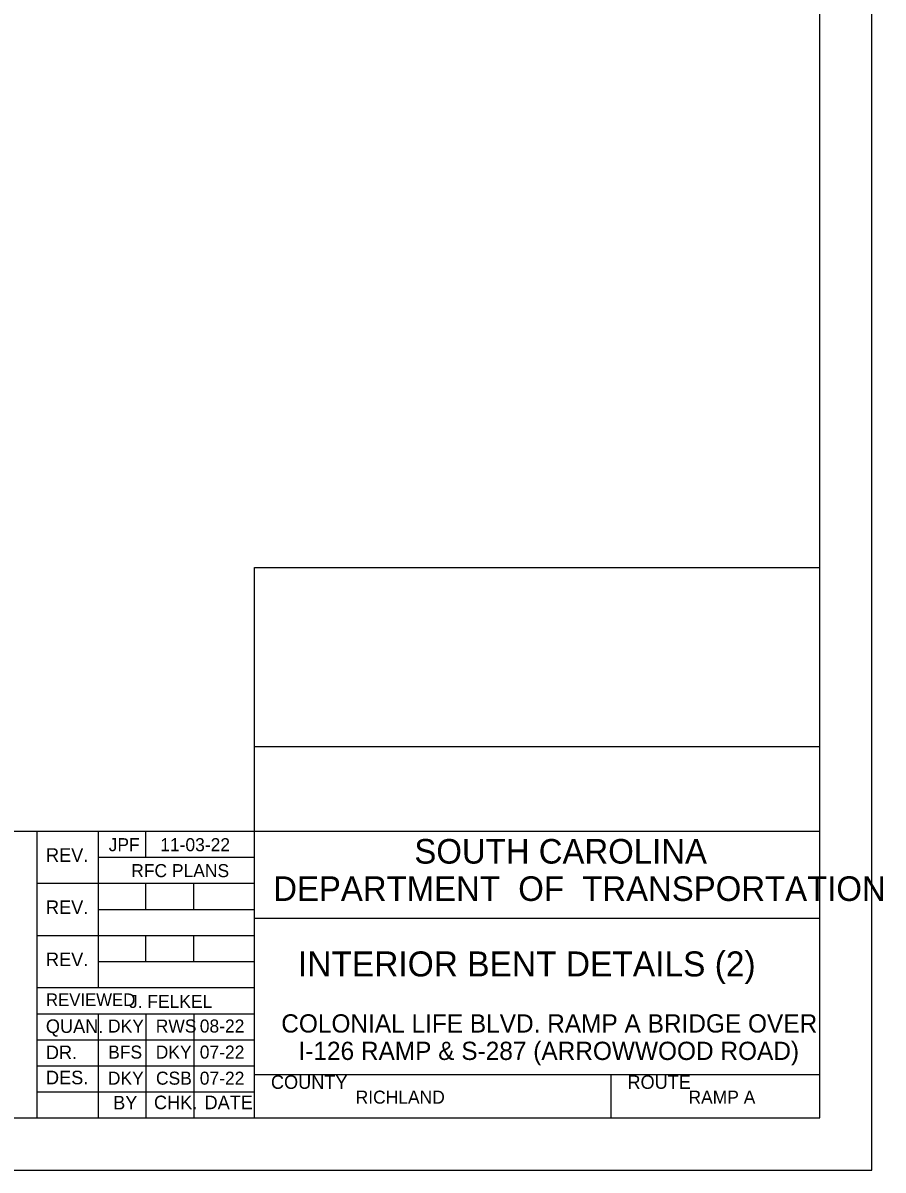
# Model space of a CAD drawing. Extents: x 1970675.2 to 1970711.3, y 796145.2 to 796167.2.
# Drawn here: x 1970703.1 to 1970711.34, y 796145.25 to 796156.25 of the extents above; entities that cross this region are included whole.
import ezdxf

# ---------------------------------------------------------------- set-up
doc = ezdxf.new("R2010")
doc.units = 0
for name, color, linetype in [('BR_BORDER LINES', 7, 'Continuous'), ('BR_TEXT', 7, 'Continuous'), ('Level 31', 7, 'Continuous')]:
    doc.layers.add(name, color=color, linetype=linetype)

msp = doc.modelspace()

# ---------------------------------------------------------------- linework, layer by layer
at = {"layer": 'BR_BORDER LINES'}
for p, q in [((1970710.736, 796145.746), (1970710.736, 796166.746)), ((1970705.319, 796145.746), (1970705.319, 796151.023)), ((1970705.319, 796151.023), (1970710.736, 796151.023)), ((1970705.319, 796149.308), (1970710.736, 796149.308)), ((1970697.87, 796148.496), (1970703.236, 796148.496)), ((1970703.236, 796145.746), (1970703.236, 796148.496)), ((1970703.236, 796148.496), (1970710.736, 796148.496)), ((1970703.819, 796148.496), (1970703.819, 796146.996)), ((1970704.277, 796148.246), (1970704.277, 796148.496)), ((1970703.819, 796148.246), (1970705.319, 796148.246)), ((1970703.236, 796147.996), (1970705.319, 796147.996)), ((1970704.277, 796147.746), (1970704.277, 796147.996)), ((1970704.736, 796147.746), (1970704.736, 796147.996)), ((1970703.819, 796147.746), (1970705.319, 796147.746)), ((1970705.319, 796147.663), (1970705.319, 796147.663)), ((1970705.319, 796147.663), (1970710.736, 796147.663)), ((1970703.236, 796147.496), (1970705.319, 796147.496)), ((1970704.277, 796147.246), (1970704.277, 796147.496)), ((1970704.736, 796147.246), (1970704.736, 796147.496)), ((1970703.819, 796147.246), (1970705.319, 796147.246)), ((1970703.236, 796146.996), (1970705.319, 796146.996)), ((1970703.236, 796146.746), (1970705.319, 796146.746)), ((1970703.819, 796146.746), (1970703.819, 796145.746)), ((1970704.277, 796146.746), (1970704.277, 796145.746)), ((1970704.736, 796146.746), (1970704.736, 796145.746)), ((1970703.236, 796146.496), (1970705.319, 796146.496)), ((1970703.236, 796146.246), (1970705.319, 796146.246)), ((1970705.319, 796146.163), (1970710.736, 796146.163)), ((1970705.417, 796146.163), (1970710.736, 796146.163)), ((1970708.736, 796145.746), (1970708.736, 796146.163)), ((1970703.236, 796145.996), (1970705.319, 796145.996)), ((1970677.07, 796145.746), (1970710.736, 796145.746))]:
    msp.add_line(p, q, dxfattribs=at)
at = {"layer": 'Level 31'}
msp.add_line((1970708.028, 796147.223), (1970708.028, 796147.223), dxfattribs=at)
msp.add_lwpolyline([(1970675.236, 796167.246), (1970675.236, 796145.246), (1970711.236, 796145.246), (1970711.236, 796167.246)], dxfattribs=at)

# ---------------------------------------------------------------- texts
at = {"layer": 'BR_TEXT'}
for s, height, p in [('REV.', 0.13, (1970703.32, 796148.202)), ('JPF', 0.125, (1970703.921, 796148.304)), ('11-03-22', 0.125, (1970704.415, 796148.304)), ('SOUTH CAROLINA', 0.23587, (1970706.851, 796148.185)), ('RFC PLANS', 0.125, (1970704.137, 796148.055)), ('DEPARTMENT  OF  TRANSPORTATION', 0.23587, (1970705.498, 796147.827)), ('REV.', 0.13, (1970703.32, 796147.702)), ('INTERIOR BENT DETAILS (2)', 0.24, (1970705.735, 796147.103)), ('REV.', 0.13, (1970703.32, 796147.202)), ('REVIEWED', 0.12, (1970703.32, 796146.82)), ('J. FELKEL', 0.125, (1970704.115, 796146.801)), ('QUAN.', 0.13, (1970703.319, 796146.561)), ('DKY', 0.125, (1970703.915, 796146.565)), ('RWS', 0.125, (1970704.372, 796146.565)), ('08-22', 0.125, (1970704.794, 796146.565)), ('COLONIAL LIFE BLVD. RAMP A BRIDGE OVER', 0.175, (1970705.575, 796146.565)), ('I-126 RAMP & S-287 (ARROWWOOD ROAD)', 0.175, (1970705.74, 796146.302)), ('DR.', 0.13, (1970703.319, 796146.31)), ('BFS', 0.125, (1970703.916, 796146.315)), ('DKY', 0.125, (1970704.372, 796146.315)), ('07-22', 0.125, (1970704.794, 796146.315)), ('DES.', 0.13, (1970703.32, 796146.069)), ('DKY', 0.125, (1970703.913, 796146.065)), ('CSB', 0.125, (1970704.374, 796146.065)), ('07-22', 0.125, (1970704.794, 796146.065)), ('COUNTY', 0.13, (1970705.476, 796146.025)), ('ROUTE', 0.13, (1970708.893, 796146.025)), ('BY', 0.13, (1970703.964, 796145.828)), ('CHK.', 0.13, (1970704.355, 796145.83)), ('DATE', 0.13, (1970704.84, 796145.83)), ('RICHLAND', 0.125, (1970706.288, 796145.883)), ('RAMP A', 0.125, (1970709.478, 796145.883))]:
    msp.add_text(s, height=height, dxfattribs=at).set_placement(p)

doc.saveas('drawing.dxf')
